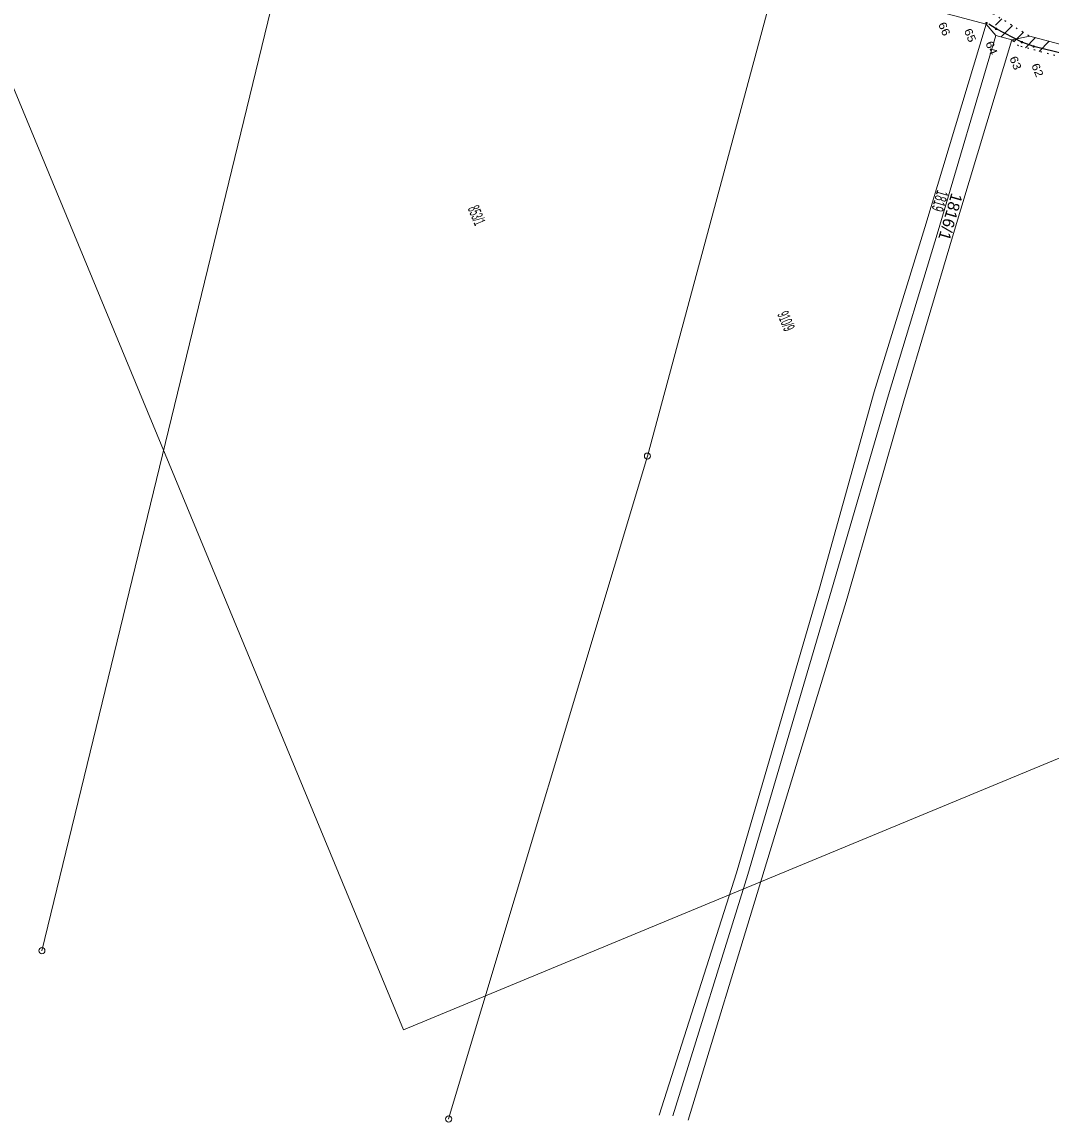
# Model space of a CAD drawing. Extents: x -687415 to -686486, y -959539 to -958099.
# Drawn here: x -686991 to -686740.3, y -959539.2 to -959271.3 of the extents above; entities that cross this region are included whole.
import ezdxf
from ezdxf.enums import TextEntityAlignment as Align

# ---------------------------------------------------------------- set-up
doc = ezdxf.new("R2010")
doc.units = 0
doc.header["$LTSCALE"] = 1.1
doc.linetypes.add('DOTTED', pattern=[1.5, 0.3, -1.2])
for name, color, linetype, lineweight in [('1', 7, 'Continuous', 13), ('2', 7, 'Continuous', 25), ('3', 7, 'Continuous', 13)]:
    doc.layers.add(name, color=color, linetype=linetype, lineweight=lineweight)

msp = doc.modelspace()

# ---------------------------------------------------------------- linework, layer by layer
at = {"layer": '1'}
for p, q in [((-686806.61, -959258.31), (-686756.11, -959271.89)), ((-686749.593, -959275.584), (-686749.455, -959276.009))]:
    msp.add_line(p, q, dxfattribs=at)
at = {"layer": '1', "linetype": 'DOTTED', "lineweight": 25}
for p, q in [((-686748.2, -959277.13), (-686749.87, -959275.64)), ((-686729.79, -959282.07), (-686748.2, -959277.13))]:
    msp.add_line(p, q, dxfattribs=at)
at = {"layer": '1'}
for points in [[(-687414.687, -958269.529), (-686898.065, -959516.766), (-686486.476, -959346.281), (-687003.099, -958099.043)], [(-686756.162, -959271.707), (-686756.162, -959271.407), (-686755.862, -959271.407), (-686755.862, -959271.707)], [(-686753.81, -959273.15), (-686753.81, -959272.85), (-686753.51, -959272.85), (-686753.51, -959273.15)], [(-686747.58, -959276.4), (-686747.58, -959276.1), (-686747.28, -959276.1), (-686747.28, -959276.4)], [(-686744.66, -959277.44), (-686744.66, -959277.14), (-686744.36, -959277.14), (-686744.36, -959277.44)]]:
    msp.add_lwpolyline(points, close=True, dxfattribs=at)
at = {"layer": '1', "linetype": 'DOTTED', "lineweight": 25}
msp.add_lwpolyline([(-686918.72, -959223.39), (-686919.1, -959226.08), (-686889.21, -959233), (-686805.83, -959255.41), (-686754.43, -959269.25), (-686745.48, -959274.75)], dxfattribs=at)
at = {"layer": '1'}
for points in [[(-686920.76, -959228.77), (-686922.24, -959234.86), (-686986.17, -959497.52)], [(-686920.76, -959228.77), (-686889.94, -959235.91), (-686806.61, -959258.31), (-686808.46, -959265.16), (-686838.63, -959377.05), (-686887.06, -959538.48)], [(-686835.76, -959537.55), (-686816.95, -959478.51), (-686796.74, -959409.22), (-686783.38, -959361.37), (-686771, -959321.37), (-686756.11, -959271.89)], [(-686756.11, -959271.89), (-686753.73, -959274.6), (-686767.78, -959322.15), (-686779.89, -959362.16), (-686793.77, -959409.67), (-686814.18, -959478.96), (-686832.4, -959537.71)], [(-686753.73, -959274.6), (-686749.87, -959275.64), (-686764.33, -959323.64), (-686776.12, -959363.56), (-686789.98, -959411.68), (-686810.72, -959479.86), (-686828.67, -959538.75)], [(-686745.48, -959274.75), (-686729.07, -959279.16), (-686711.5, -959282.77), (-686634.54, -959292.77), (-686594.27, -959295.98), (-686593.21, -959299.09)]]:
    msp.add_lwpolyline(points, dxfattribs=at)
for centre, radius in [((-686838.63, -959377.05), 0.75), ((-686838.63, -959377.05), 0.015), ((-686986.17, -959497.52), 0.75), ((-686986.17, -959497.52), 0.015), ((-686887.06, -959538.48), 0.75), ((-686887.06, -959538.48), 0.015)]:
    msp.add_circle(centre, radius, dxfattribs=at)
at = {"layer": '2', "lineweight": 13}
msp.add_line((-686749.87, -959275.64), (-686745.48, -959274.75), dxfattribs=at)
at = {"layer": '2'}
for points in [[(-686747.43, -959276.25), (-686753.66, -959273), (-686755.479, -959271.813)], [(-686674.327, -959288.232), (-686705.58, -959285.51), (-686729.67, -959280.93), (-686744.51, -959277.29), (-686747.43, -959276.25)]]:
    msp.add_lwpolyline(points, dxfattribs=at)
at = {"layer": '3'}
for p, q in [((-686753.789, -959272.1), (-686752.268, -959270.578)), ((-686752.404, -959274.957), (-686749.64, -959272.193)), ((-686749.328, -959276.123), (-686747.012, -959273.808)), ((-686746.537, -959277.576), (-686745.41, -959276.448)), ((-686745.351, -959276.39), (-686744.086, -959275.124)), ((-686743.192, -959278.473), (-686740.742, -959276.023))]:
    msp.add_line(p, q, dxfattribs=at)

# ---------------------------------------------------------------- texts
at = {"layer": '1'}
for s, height, rotation, width, p in [('66', 1.95, 292.5, 1.15, (-686767.823, -959271.844)), ('65', 1.95, 292.5, 1.15, (-686761.536, -959273.397)), ('64', 1.95, 292.5, 1.15, (-686756.323, -959276.467)), ('63', 1.95, 292.5, 1.15, (-686750.467, -959280.126)), ('62', 1.95, 292.5, 1.15, (-686745.13, -959281.865)), ('1819', 2.85, 253.8, 0.6, (-686767.993, -959312.096))]:
    msp.add_text(s, height=height, rotation=rotation, dxfattribs=dict(at, width=width)).set_placement(p)
msp.add_text('1816/1', height=2.85, rotation=253.8, dxfattribs=at).set_placement((-686764.533, -959312.791))
at = {"layer": '1', "width": 0.5}
for s, p in [('853/1', (-686881.539, -959318.955)), ('910/9', (-686806.143, -959344.689))]:
    msp.add_text(s, height=2.85, rotation=292.5, dxfattribs=at).set_placement(p, align=Align.CENTER)

doc.saveas('drawing.dxf')
